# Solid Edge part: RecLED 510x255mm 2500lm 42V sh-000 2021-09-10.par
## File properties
Author: radoslaw.kuczynski
Template: iso metric part.par
Last saved by: radoslaw.kuczynski
Revision: 1
Application: Solid Edge
Gęstość: 0.000 kg/m^3
Dokładność: 0.990
Username: radoslaw.kuczynski
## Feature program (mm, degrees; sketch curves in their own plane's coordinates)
body "unnamed Body 1"
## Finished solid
Body 1: solid body, 3381 faces, 9065 edges, 5916 vertices, 3 separate solids.
  Faces by surface: plane 2508, cylinder 605, spline 160, cone 52, torus 22, sphere 20, spun 14
  Edges by curve: line 7233, circle 1048, curve on surface 564, ellipse 132, spline 76, intersection 12
Bounding box of the edges (mm; curved faces can reach further): 510.000 x 4.500 x 254.500, from (-255, -3.5, -127.25) to (255, 1, 127.25).
Cylindrical faces by radius (mm): R0.2 x78, R0.2002 x4, R0.2169 x6, R0.25 x24, R0.3 x4, R0.3373 x6, R0.4 x16, R0.4006 x4, R0.4008 x4, R0.525 x4, R0.6 x24, R1 x14, R1.0894 x4, R1.1 x28, R2.15 x20, R3 x183, R5 x180, R10 x2
Conical faces (half-angle, radius in mm at the cone's reference point): 0.5 deg R0.5056 x8, 0.5 deg R1.0082 x8, 1 deg R0.5511 x4, 10 deg R0.2132 x4, 10 deg R0.4132 x4, 18.4844 deg R1.0657 x8, 27.363 deg R0.6214 x4, 45 deg R0.575 x4, 45 deg R0.625 x8
Toroidal faces (ring radius, tube radius in mm): R0.1 r0.2 x2, R0.8 r0.2 x8, R0.8522 r0.3 x4, R0.9002 r0.2 x2, R0.9018 r0.2 x2, R1.3 r0.2 x4
Spherical faces by radius (mm): R0.2 x16, R0.6 x4
Planar faces by outward normal: +x 342, +y 23, +z 347, -x 354, -y 375, -z 339, oblique 728
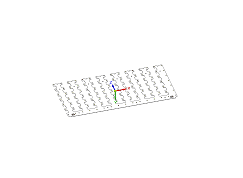
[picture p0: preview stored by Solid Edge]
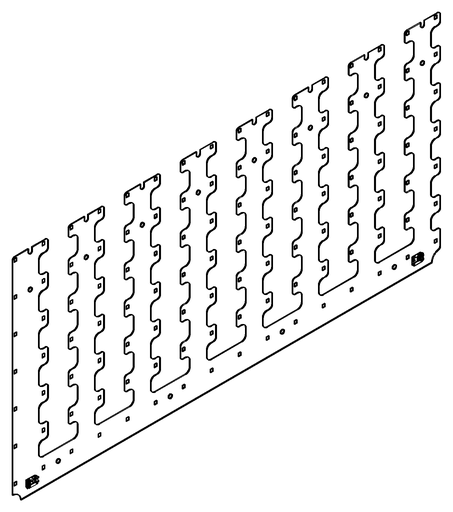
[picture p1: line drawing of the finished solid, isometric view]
